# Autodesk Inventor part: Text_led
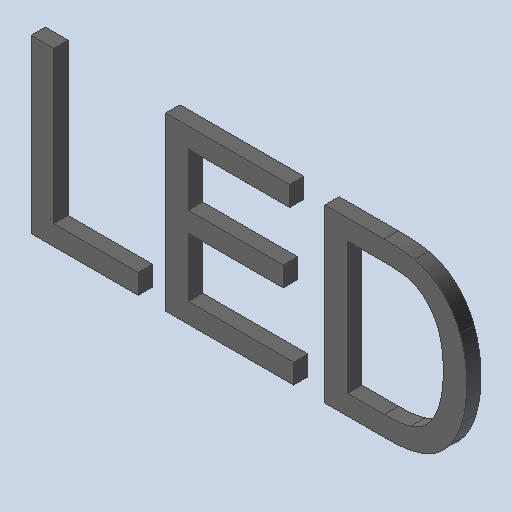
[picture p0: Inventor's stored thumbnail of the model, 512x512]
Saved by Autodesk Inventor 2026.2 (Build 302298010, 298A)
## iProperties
Created: 2026-10
Part Number: Text_led
Material: Générique
Document SubType Name: Modeling
Designer: mel
Density: 1 g/cm^3
Appearance: Par défaut
Author: mel
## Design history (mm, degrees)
feature "Base1"
feature "Base2"
feature "Base3"
node "Solide1"
node "Solide2"
node "Solide3"
